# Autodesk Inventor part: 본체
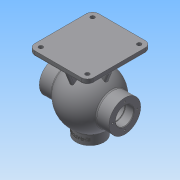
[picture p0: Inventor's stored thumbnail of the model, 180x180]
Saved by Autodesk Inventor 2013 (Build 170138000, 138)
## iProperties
Created: 2018-06
Part Number: 본체
Material: 일반
Document SubType Name: Modeling
Designer: Administrator
Density: 1 g/cm^3
Author: Administrator
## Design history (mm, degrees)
sketch "스케치5"
  geometry: L1 (-53, 0)-(53, 0); A1 r 53 centre (0, 0) between (53, 0) and (-53, 0); A2 r 43 centre (0, 0) between (43, 0) and (-43, 0); 2 further points
  constraints: 4 point on circle, 3 coincident, 2 centre point, 2 end point, 2 point on line, 1 horizontal, 1 midpoint
  dimensions: "d19" = 106 diameter of A1; "d20" = 86 diameter of A2
revolve "회전2" sketch "스케치5" stored, may be unused: angle "d21" = 90 deg
sketch "스케치6"
  geometry: L1 (53, 0)-(68, 0); L2 (68, 0)-(68, 31); L3 (68, 31)-(42.988, 31); C1 r 43 at (0, 0) reference; A1 r 53 centre (0, 0) between (42.988, 31) and (53, 0) reference; 1 further point
  constraints: 6 end point, 2 point on circle, 1 horizontal, 1 parallel, 1 point on line, 1 vertical
  dimensions: "d22" = 62 diameter of L2.end L1; "d24" = 68 distance from line of L2 point (0, 0)
revolve "회전3" sketch "스케치6" stored, may be unused: angle "d25" = 90 deg
sketch "스케치9"
  geometry: L1 (68, -31)-(68, 31) reference; L2 (43, 0)-(68, 0); L3 (68, 0)-(68, 17.5); L4 (68, 17.5)-(52, 17.5); L5 (52, 17.5)-(52, 18.5); L6 (52, 18.5)-(50.25, 18.5); L7 (50.25, 18.5)-(50.25, 17.5); L8 (50.25, 17.5)-(39.278, 17.5); A1 r 43 centre (0, 0) between (43, 0) and (39.278, 17.5) reference; 1 further point
  constraints: 14 end point, 2 collinear, 2 parallel, 2 perpendicular, 2 point on circle, 2 point on line, 1 midpoint
  dimensions: "d27" = 35 diameter of L3.end L2; "d136" = 16 distance of L3.end L4.end; "d137" = 1.75 distance between parallel lines of L5 L7; "d138" = 37 diameter of L5.end L2; "d139" = 35 diameter of L7.end L2
revolve "회전4" sketch "스케치9" stored, may be unused: angle "d31" = 90 deg
sketch "스케치12"
  geometry: C1 r 31 at (0, 0) reference; C2 r 17.5 at (0, 0)
  constraints: 1 centre point, 1 coincident
  dimensions: "d36" = 35 diameter of C2
extrude "돌출1" cut sketch "스케치12" stored distance "d37" = 10; taper "d38" = 0 deg
sketch "스케치14"
  geometry: C1 r 31 at (0, 0) reference; 1 further point
  constraints: 1 vertical alignment
  dimensions: "d44" = 22.5 distance of point (0, 22.5) C1.centre
hole "구멍1" sketch "스케치14" at (0, 22.5) diameter "d45" = 3.242; stored, may be unused: countersink angle "d49" = 90 deg, drill point angle "d51" = 118 deg; dims "d46" = 12, "d47" = 35, "d48" = 16, "d50" = 15
sketch "스케치15"
  geometry: C1 r 31 at (0, 0) reference; 1 further point
  constraints: 1 vertical alignment
  dimensions: "d56" = 24 distance of C1.centre point (0, 24)
hole "구멍2" sketch "스케치15" at (0, 24) diameter "d57" = 3.242; stored, may be unused: countersink angle "d61" = 90 deg, drill point angle "d63" = 118 deg; dims "d58" = 16, "d59" = 35, "d60" = 16, "d62" = 19
node "작업 평면2"
sketch "스케치16"
  geometry: C1 r 27 at (0, 0); 1 further point
  constraints: 1 centre point, 1 coincident
  dimensions: "d68" = 54 diameter of C1
extrude "돌출2" join sketch "스케치16" stored distance "d69" = 54 (= d68); taper "d70" = 0 deg
sketch "스케치17"
  geometry: C1 r 27 at (0, 0) reference; C2 r 13 at (0, 0)
  constraints: 1 centre point, 1 coincident
  dimensions: "d71" = 26 diameter of C2
extrude "돌출3" cut sketch "스케치17" stored distance "d72" = 10; taper "d73" = 0 deg
sketch "스케치18"
  geometry: C1 r 13 at (0, 0) reference; 1 further point
  constraints: 1 vertical alignment
  dimensions: "d74" = 20 distance of C1.centre point (0, 20)
hole "구멍3" sketch "스케치18" at (0, 20) diameter "d75" = 3.242; stored, may be unused: countersink angle "d79" = 90 deg, drill point angle "d81" = 118 deg; dims "d76" = 9, "d77" = 35, "d78" = 16, "d80" = 11
chamfer "모따기4" distance "d88" = 1; stored, may be unused: second distance "d89" = 2, angle "d90" = 45 deg
fillet "모깎기1" dims "d91" = 3
sketch "스케치19"
  geometry: L1 (57.5, 75)-(-57.5, 75); L2 (-57.5, 75)-(-57.5, 85); L3 (-57.5, 85)-(57.5, 85); L4 (57.5, 85)-(57.5, 75); 2 further points
  constraints: 8 end point, 2 parallel, 1 horizontal, 1 midpoint, 1 perpendicular, 1 vertical alignment
  dimensions: "d92" = 115 distance of L2.end L3.end; "d93" = 10 distance of L1.end L2.end; "d94" = 85 distance from line of point (0, 0) L3
extrude "돌출4" join sketch "스케치19" stored distance "d95" = 125; taper "d96" = 0 deg
sketch "스케치20"
  geometry: L1 (0, 0)-(115, 0) reference; L2 (61.5, -115)-(53.5, -115); L3 (53.5, -115)-(53.5, -10); L4 (53.5, -10)-(61.5, -10); L5 (61.5, -10)-(61.5, -115); L6 (61.5, -115)-(53.5, -10); L7 (53.5, -115)-(61.5, -10); 1 further point
  constraints: 12 end point, 2 midpoint, 2 parallel, 1 horizontal, 1 perpendicular
  dimensions: "d97" = 10 distance between parallel lines of L1 L4; "d98" = 8 distance of L3.end L4.end
extrude "돌출5" join sketch "스케치20" stored distance "d99" = 125; taper "d100" = 0 deg
feature "면 기울기1" dims angle "d101" = 22 deg
sketch "스케치21"
  geometry: L1 (-47.5, 75)-(-39.576, 55.388); L2 (57.5, 75)-(-57.5, 75) reference; L3 (-57.5, 75)-(-57.5, 85) reference; 1 further point
  constraints: 2 end point, 1 point on line
  dimensions: "d102" = 22 deg angle of L1 L3; "d103" = 10 distance from line of L1.start L3
feature "리브1" sketch "스케치21" dims "d104" = 1, "d105" = 8, "d106" = 0, "d107" = 0, "d108" = 1, "d109" = 1
node "작업 평면3"
sketch "스케치22"
  geometry: L1 (27, 0)-(27, 17.714) reference; L2 (27, 0)-(-27, 0) reference; 2 further points
  constraints: 1 other
  dimensions: "d110" = 27 distance from line of point (0, 10) L1; "d111" = 10 distance from line of L2 point (0, 10)
feature "엠보싱1" sketch "스케치22" dims "d112" = 0.5, "d113" = 0
fillet "모깎기2" dims "d114" = 3
fillet "모깎기3" dims "d115" = 3
fillet "모깎기4" dims "d116" = 12
sketch "스케치24"
  geometry: A1 r 12 centre (91, -113) between (91, -125) and (103, -113) reference; A2 r 12 centre (91, -12) between (103, -12) and (91, 0) reference; A3 r 12 centre (0, -12) between (0, 0) and (-12, -12) reference; A4 r 12 centre (0, -113) between (-12, -113) and (0, -125) reference; 5 further points
  constraints: 4 coincident
hole "구멍4" sketch "스케치24" at (0, -12), (91, -12), (91, -113), (0, -113) diameter "d122" = 8; stored, may be unused: countersink angle "d126" = 90 deg, drill point angle "d128" = 118 deg; dims "d123" = 9, "d124" = 12, "d125" = 3, "d127" = 11
fillet "모깎기5" dims "d129" = 3
chamfer "모따기5" distance "d143" = 1; stored, may be unused: second distance "d144" = 2, angle "d145" = 45 deg
node "솔리드2"
mirror "대칭1"
pattern_circular "원형 패턴1" dims angle "d53" = 360 deg
pattern_circular "원형 패턴3" dims angle "d83" = 360 deg
mirror "대칭2"
pattern_circular "원형 패턴4" dims angle "d141" = 360 deg
other parameters: "d67" = -65
